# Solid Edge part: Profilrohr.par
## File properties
Username: ahadarics
Dokumentum tartalom típus: 0
Author: ahadarics
Last saved by: ahadarics
Revision: 78
Sűrűség: 0,000 kg/m^3
Pontosság: 0,990
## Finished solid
Body 1: solid body, 95 faces, 278 edges, 184 vertices.
  Faces by surface: plane 48, cylinder 47
  Edges by curve: line 184, circle 94
Bounding box of the edges (mm): 65.500 x 65.500 x 31.000, from (-32.75, -32.75, 0) to (32.75, 32.75, 31).
Cylindrical faces by radius (mm): R0.15 x20, R0.25 x20, R6.5 x2, R8 x4, R25 x1
Planar faces by outward normal: +x 11, +y 12, +z 1, -x 11, -y 12, -z 1
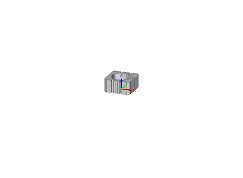
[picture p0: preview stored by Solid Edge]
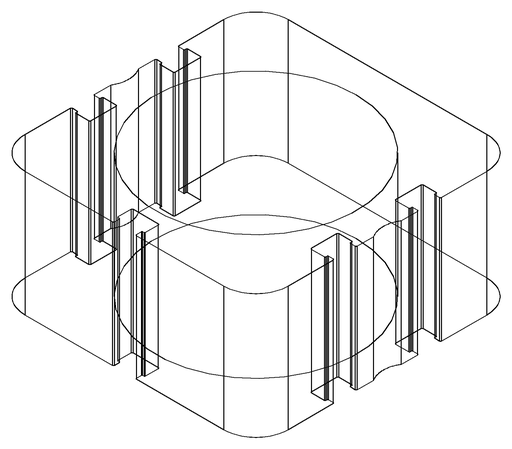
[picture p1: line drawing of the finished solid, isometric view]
